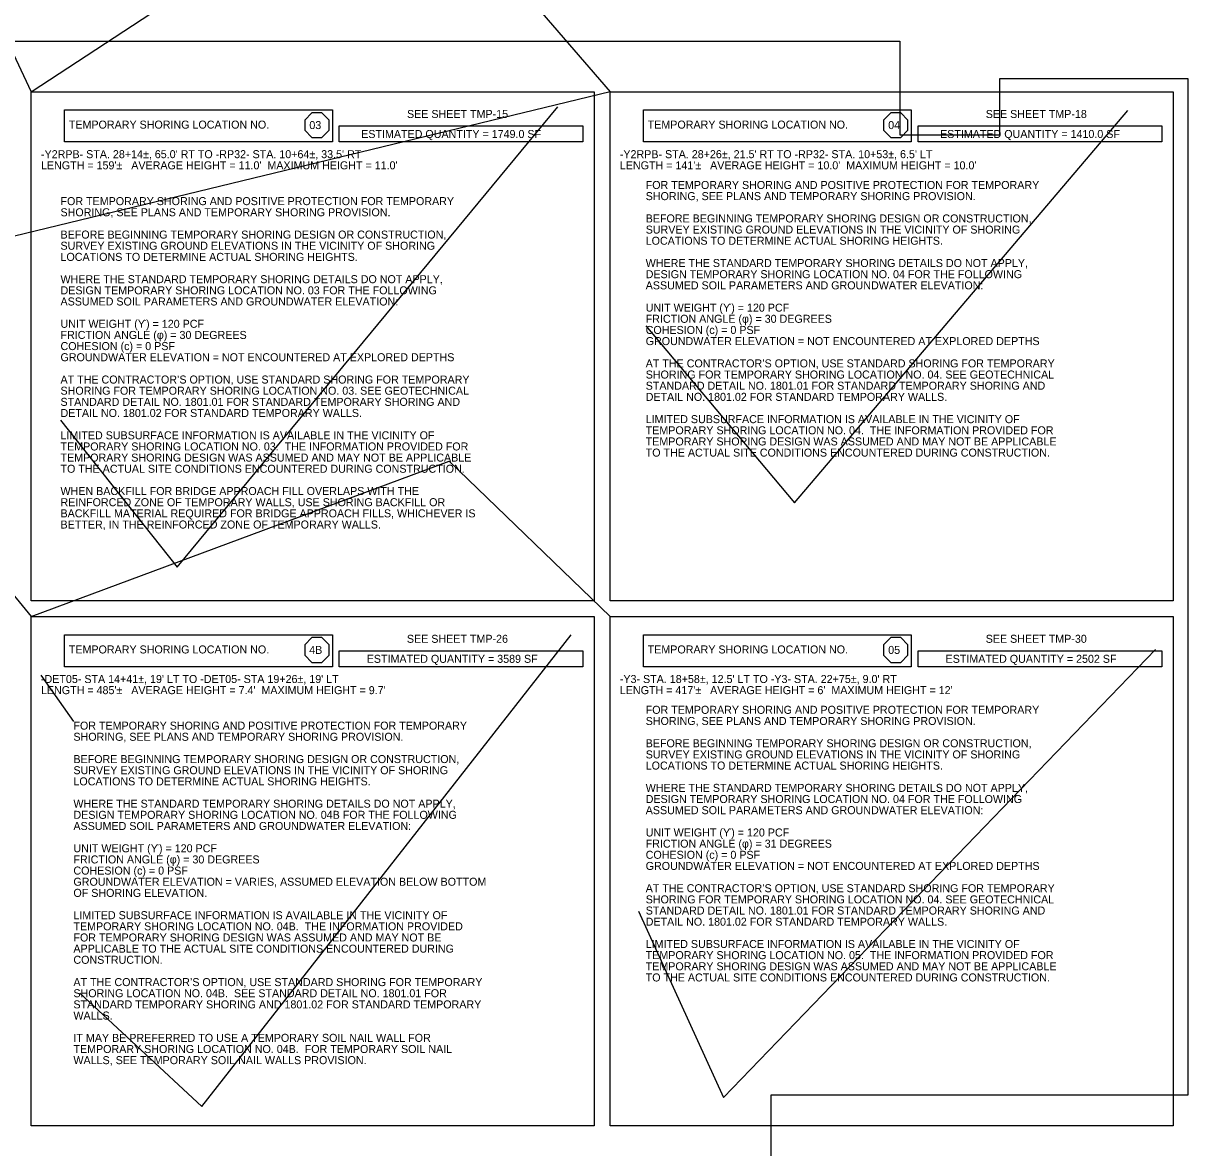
# Model space of a CAD drawing. Extents: x 2487012 to 2497594, y 369516 to 371986.
# Drawn here: x 2491299 to 2492290, y 370340 to 371297 of the extents above; entities that cross this region are included whole.
import ezdxf

# ---------------------------------------------------------------- set-up
doc = ezdxf.new("R2010")
doc.units = 0
for name, color, linetype in [('Scratch_Level_2', 7, 'Continuous'), ('Scratch_Level_4', 7, 'Continuous'), ('Scratch_Level_5', 7, 'Continuous'), ('Scratch_Level_6', 7, 'Continuous'), ('TC LABEL TEMP SHORING', 7, 'Continuous'), ('TC SHEET BORDER LINE THIN', 7, 'Continuous'), ('TC SHEET LAYOUT SHAPE', 7, 'Continuous'), ('TC SHEET TEXT', 7, 'Continuous')]:
    doc.layers.add(name, color=color, linetype=linetype)

msp = doc.modelspace()

# ---------------------------------------------------------------- linework, layer by layer
at = {"layer": 'Scratch_Level_2'}
for points in [[(2491330.49, 370959.46), (2491429.77, 370834.2), (2491753.99, 371226.17)], [(2491828.78, 371039.67), (2491955.41, 370889.07), (2492239.4, 371223.09)], [(2491347.09, 370471.61), (2491450.87, 370375.03), (2491765.44, 370776.66)]]:
    msp.add_lwpolyline(points, dxfattribs=at)
at = {"layer": 'Scratch_Level_4'}
msp.add_lwpolyline([(2491822.75, 370541.29), (2491895.16, 370382.73), (2492262.82, 370764.24)], dxfattribs=at)
at = {"layer": 'Scratch_Level_5'}
msp.add_line((2491313.86, 370742.45), (2491341.49, 370702.77), dxfattribs=at)
at = {"layer": 'Scratch_Level_6'}
msp.add_lwpolyline([(2490800.31, 371282.27), (2490812.63, 371239.13), (2491214.19, 371433.43), (2491305.53, 371239.13), (2491620.29, 371445.42), (2491798.43, 371239.13), (2490627, 370955.22), (2490812.63, 370792.26), (2491172.91, 370953.89), (2491305.53, 370792.26), (2491661.57, 370924.58), (2491798.43, 370792.26)], dxfattribs=at)
at = {"layer": 'TC LABEL TEMP SHORING'}
for p, q in [((2491544.49, 371221.17), (2491538.4, 371215.01)), ((2491538.4, 371215.01), (2491538.4, 371206.28)), ((2491553.1, 371221.17), (2491544.49, 371221.17)), ((2491559.18, 371215.01), (2491553.1, 371221.17)), ((2491559.18, 371206.28), (2491559.18, 371215.01)), ((2492037.38, 371221.17), (2492031.3, 371215.01)), ((2492031.3, 371215.01), (2492031.3, 371206.28)), ((2492045.99, 371221.17), (2492037.38, 371221.17)), ((2492052.08, 371215.01), (2492045.99, 371221.17)), ((2492052.08, 371206.28), (2492052.08, 371215.01)), ((2491538.4, 371206.28), (2491544.49, 371200.12)), ((2491553.1, 371200.12), (2491559.18, 371206.28)), ((2492031.3, 371206.28), (2492037.38, 371200.12)), ((2492045.99, 371200.12), (2492052.08, 371206.28)), ((2491544.49, 371200.12), (2491553.1, 371200.12)), ((2492037.38, 371200.12), (2492045.99, 371200.12)), ((2491544.49, 370774.3), (2491538.4, 370768.13)), ((2491538.4, 370768.13), (2491538.4, 370759.41)), ((2491553.1, 370774.3), (2491544.49, 370774.3)), ((2491559.18, 370768.13), (2491553.1, 370774.3)), ((2491559.18, 370759.41), (2491559.18, 370768.13)), ((2492037.38, 370774.3), (2492031.3, 370768.13)), ((2492031.3, 370768.13), (2492031.3, 370759.41)), ((2492045.99, 370774.3), (2492037.38, 370774.3)), ((2492052.08, 370768.13), (2492045.99, 370774.3)), ((2492052.08, 370759.41), (2492052.08, 370768.13)), ((2491538.4, 370759.41), (2491544.49, 370753.24)), ((2491553.1, 370753.24), (2491559.18, 370759.41)), ((2492031.3, 370759.41), (2492037.38, 370753.24)), ((2492045.99, 370753.24), (2492052.08, 370759.41)), ((2491544.49, 370753.24), (2491553.1, 370753.24)), ((2492037.38, 370753.24), (2492045.99, 370753.24))]:
    msp.add_line(p, q, dxfattribs=at)
at = {"layer": 'TC SHEET BORDER LINE THIN'}
for points in [[(2491305.53, 371239.13), (2491784.97, 371239.13), (2491784.97, 370805.5), (2491305.53, 370805.5)], [(2491798.43, 371239.13), (2492277.87, 371239.13), (2492277.87, 370805.5), (2491798.43, 370805.5)], [(2491334.02, 371223.55), (2491562.07, 371223.55), (2491562.07, 371196.29), (2491334.02, 371196.29)], [(2491826.91, 371223.55), (2492054.97, 371223.55), (2492054.97, 371196.29), (2491826.91, 371196.29)], [(2491567.83, 371209.92), (2491775.3, 371209.92), (2491775.3, 371196.29), (2491567.83, 371196.29)], [(2492060.73, 371209.92), (2492268.2, 371209.92), (2492268.2, 371196.29), (2492060.73, 371196.29)], [(2491305.53, 370792.26), (2491784.97, 370792.26), (2491784.97, 370358.63), (2491305.53, 370358.63)], [(2491798.43, 370792.26), (2492277.87, 370792.26), (2492277.87, 370358.63), (2491798.43, 370358.63)], [(2491334.02, 370776.68), (2491562.07, 370776.68), (2491562.07, 370749.42), (2491334.02, 370749.42)], [(2491826.91, 370776.68), (2492054.97, 370776.68), (2492054.97, 370749.42), (2491826.91, 370749.42)], [(2491567.83, 370763.05), (2491775.3, 370763.05), (2491775.3, 370749.42), (2491567.83, 370749.42)], [(2492060.73, 370763.05), (2492268.2, 370763.05), (2492268.2, 370749.42), (2492060.73, 370749.42)]]:
    msp.add_lwpolyline(points, close=True, dxfattribs=at)
at = {"layer": 'TC SHEET LAYOUT SHAPE'}
msp.add_lwpolyline([(2490800.31, 370690.84), (2490800.31, 371000.16), (2490800.31, 371272.27), (2490810.31, 371282.27), (2491253.33, 371282.27), (2491724.31, 371282.27), (2492045.31, 371282.27), (2492045.31, 371202.27), (2492130.31, 371202.27), (2492130.31, 371250.27), (2492290.31, 371250.27), (2492290.31, 370915.3), (2492290.31, 370636.1), (2492290.31, 370384.77), (2491935.31, 370384.77), (2491935.31, 370242.27), (2491562.13, 370242.27), (2491392.66, 370242.27), (2491039.89, 370242.27), (2490800.31, 370242.27)], close=True, dxfattribs=at)

# ---------------------------------------------------------------- texts
at = {"layer": 'TC LABEL TEMP SHORING'}
for s, p in [('03', (2491542.38, 371207.28)), ('04', (2492035.28, 371207.28)), ('4B', (2491542.27, 370760.41)), ('05', (2492035.28, 370760.41))]:
    msp.add_text(s, height=6.814, dxfattribs=at).set_placement(p)
at = {"layer": 'TC SHEET BORDER LINE THIN'}
for s, height, p in [('FOR TEMPORARY SHORING AND POSITIVE PROTECTION FOR TEMPORARY ', 6.8137, (2491828.78, 371156.28)), ('SHORING, SEE PLANS AND TEMPORARY SHORING PROVISION.', 6.8137, (2491828.78, 371146.79)), ('FOR TEMPORARY SHORING AND POSITIVE PROTECTION FOR TEMPORARY ', 6.8137, (2491330.49, 371142.53)), ('SHORING, SEE PLANS AND TEMPORARY SHORING PROVISION.', 6.8137, (2491330.49, 371133.04)), ('BEFORE BEGINNING TEMPORARY SHORING DESIGN OR CONSTRUCTION, ', 6.8137, (2491828.78, 371127.8)), ('SURVEY EXISTING GROUND ELEVATIONS IN THE VICINITY OF SHORING ', 6.8137, (2491828.78, 371118.3)), ('BEFORE BEGINNING TEMPORARY SHORING DESIGN OR CONSTRUCTION, ', 6.8137, (2491330.49, 371114.05)), ('LOCATIONS TO DETERMINE ACTUAL SHORING HEIGHTS.', 6.8137, (2491828.78, 371108.81)), ('SURVEY EXISTING GROUND ELEVATIONS IN THE VICINITY OF SHORING ', 6.8137, (2491330.49, 371104.55)), ('LOCATIONS TO DETERMINE ACTUAL SHORING HEIGHTS.', 6.8137, (2491330.49, 371095.06)), ('WHERE THE STANDARD TEMPORARY SHORING DETAILS DO NOT APPLY, ', 6.8137, (2491828.78, 371089.82)), ('DESIGN TEMPORARY SHORING LOCATION NO. 04 FOR THE FOLLOWING ', 6.8137, (2491828.78, 371080.33)), ('WHERE THE STANDARD TEMPORARY SHORING DETAILS DO NOT APPLY, ', 6.8137, (2491330.49, 371076.07)), ('DESIGN TEMPORARY SHORING LOCATION NO. 03 FOR THE FOLLOWING ', 6.8137, (2491330.49, 371066.57)), ('ASSUMED SOIL PARAMETERS AND GROUNDWATER ELEVATION:', 6.8137, (2491828.78, 371070.83)), ('ASSUMED SOIL PARAMETERS AND GROUNDWATER ELEVATION:', 6.8137, (2491330.49, 371057.08)), ('UNIT WEIGHT (ϒ) = 120 PCF ', 6.8137, (2491828.78, 371051.84)), ('UNIT WEIGHT (ϒ) = 120 PCF ', 6.8137, (2491330.49, 371038.09)), ('FRICTION ANGLE (φ) = 30 DEGREES ', 6.8137, (2491828.78, 371042.35)), ('FRICTION ANGLE (φ) = 30 DEGREES ', 6.8137, (2491330.49, 371028.6)), ('COHESION (c) = 0 PSF ', 6.8137, (2491828.78, 371032.85)), ('COHESION (c) = 0 PSF ', 6.8137, (2491330.49, 371019.1)), ('GROUNDWATER ELEVATION = NOT ENCOUNTERED AT EXPLORED DEPTHS', 6.8137, (2491828.78, 371023.36)), ('GROUNDWATER ELEVATION = NOT ENCOUNTERED AT EXPLORED DEPTHS', 6.8137, (2491330.49, 371009.61)), ('AT THE CONTRACTOR’S OPTION, USE STANDARD SHORING FOR TEMPORARY ', 6.8137, (2491828.78, 371004.37)), ('AT THE CONTRACTOR’S OPTION, USE STANDARD SHORING FOR TEMPORARY ', 6.8137, (2491330.49, 370990.62)), ('SHORING FOR TEMPORARY SHORING LOCATION NO. 04. SEE GEOTECHNICAL ', 6.8137, (2491828.78, 370994.88)), ('SHORING FOR TEMPORARY SHORING LOCATION NO. 03. SEE GEOTECHNICAL ', 6.8137, (2491330.49, 370981.13)), ('STANDARD DETAIL NO. 1801.01 FOR STANDARD TEMPORARY SHORING AND ', 6.8137, (2491828.78, 370985.38)), ('STANDARD DETAIL NO. 1801.01 FOR STANDARD TEMPORARY SHORING AND ', 6.8137, (2491330.49, 370971.63)), ('DETAIL NO. 1801.02 FOR STANDARD TEMPORARY WALLS.', 6.8137, (2491828.78, 370975.89)), ('DETAIL NO. 1801.02 FOR STANDARD TEMPORARY WALLS.', 6.8137, (2491330.49, 370962.14)), ('LIMITED SUBSURFACE INFORMATION IS AVAILABLE IN THE VICINITY OF ', 6.8137, (2491828.78, 370956.9)), ('LIMITED SUBSURFACE INFORMATION IS AVAILABLE IN THE VICINITY OF ', 6.8137, (2491330.49, 370943.15)), ('TEMPORARY SHORING LOCATION NO. 04.  THE INFORMATION PROVIDED FOR ', 6.8137, (2491828.78, 370947.4)), ('TEMPORARY SHORING DESIGN WAS ASSUMED AND MAY NOT BE APPLICABLE ', 6.8137, (2491828.78, 370937.91)), ('TEMPORARY SHORING LOCATION NO. 03.  THE INFORMATION PROVIDED FOR ', 6.8137, (2491330.49, 370933.65)), ('TO THE ACTUAL SITE CONDITIONS ENCOUNTERED DURING CONSTRUCTION.', 6.8137, (2491828.78, 370928.42)), ('TEMPORARY SHORING DESIGN WAS ASSUMED AND MAY NOT BE APPLICABLE ', 6.8137, (2491330.49, 370924.16)), ('TO THE ACTUAL SITE CONDITIONS ENCOUNTERED DURING CONSTRUCTION.', 6.8137, (2491330.49, 370914.66)), ('WHEN BACKFILL FOR BRIDGE APPROACH FILL OVERLAPS WITH THE ', 6.8137, (2491330.49, 370895.68)), ('REINFORCED ZONE OF TEMPORARY WALLS, USE SHORING BACKFILL OR ', 6.8137, (2491330.49, 370886.18)), ('BACKFILL MATERIAL REQUIRED FOR BRIDGE APPROACH FILLS, WHICHEVER IS ', 6.8137, (2491330.49, 370876.69)), ('BETTER, IN THE REINFORCED ZONE OF TEMPORARY WALLS.', 6.8137, (2491330.49, 370867.19)), ('SHORING, SEE PLANS AND TEMPORARY SHORING PROVISION.', 6.8137, (2491828.78, 370699.91)), ('FOR TEMPORARY SHORING AND POSITIVE PROTECTION FOR TEMPORARY ', 6.8137, (2491828.78, 370709.41)), ('FOR TEMPORARY SHORING AND POSITIVE PROTECTION FOR TEMPORARY', 6.8137, (2491341.49, 370695.95)), ('SHORING, SEE PLANS AND TEMPORARY SHORING PROVISION. ', 6.8137, (2491341.49, 370686.46)), ('BEFORE BEGINNING TEMPORARY SHORING DESIGN OR CONSTRUCTION, ', 6.8137, (2491828.78, 370680.92)), ('SURVEY EXISTING GROUND ELEVATIONS IN THE VICINITY OF SHORING ', 6.8137, (2491828.78, 370671.43)), ('BEFORE BEGINNING TEMPORARY SHORING DESIGN OR CONSTRUCTION,', 6.8137, (2491341.49, 370667.47)), ('LOCATIONS TO DETERMINE ACTUAL SHORING HEIGHTS.', 6.8137, (2491828.78, 370661.94)), ('SURVEY EXISTING GROUND ELEVATIONS IN THE VICINITY OF SHORING', 6.8137, (2491341.49, 370657.98)), ('LOCATIONS TO DETERMINE ACTUAL SHORING HEIGHTS. ', 6.8137, (2491341.49, 370648.48)), ('WHERE THE STANDARD TEMPORARY SHORING DETAILS DO NOT APPLY, ', 6.8137, (2491828.78, 370642.95)), ('DESIGN TEMPORARY SHORING LOCATION NO. 04 FOR THE FOLLOWING ', 6.8137, (2491828.78, 370633.45)), ('WHERE THE STANDARD TEMPORARY SHORING DETAILS DO NOT APPLY,', 6.8137, (2491341.49, 370629.49)), ('ASSUMED SOIL PARAMETERS AND GROUNDWATER ELEVATION:', 6.8137, (2491828.78, 370623.96)), ('ASSUMED SOIL PARAMETERS AND GROUNDWATER ELEVATION: ', 6.8137, (2491341.49, 370610.5)), ('DESIGN TEMPORARY SHORING LOCATION NO. 04B FOR THE FOLLOWING ', 6.8137, (2491341.49, 370620)), ('UNIT WEIGHT (ϒ) = 120 PCF ', 6.8137, (2491828.78, 370604.97)), ('UNIT WEIGHT (ϒ) = 120 PCF ', 6.8137, (2491341.49, 370591.52)), ('FRICTION ANGLE (φ) = 31 DEGREES ', 6.8137, (2491828.78, 370595.48)), ('FRICTION ANGLE (φ) = 30 DEGREES ', 6.8137, (2491341.49, 370582.02)), ('COHESION (c) = 0 PSF ', 6.8137, (2491828.78, 370585.98)), ('COHESION (c) = 0 PSF ', 6.8137, (2491341.49, 370572.53)), ('GROUNDWATER ELEVATION = NOT ENCOUNTERED AT EXPLORED DEPTHS', 6.8137, (2491828.78, 370576.49)), ('GROUNDWATER ELEVATION = VARIES, ASSUMED ELEVATION BELOW BOTTOM ', 6.8137, (2491341.49, 370563.03)), ('OF SHORING ELEVATION. ', 6.8137, (2491341.49, 370553.54)), ('AT THE CONTRACTOR’S OPTION, USE STANDARD SHORING FOR TEMPORARY ', 6.8137, (2491828.78, 370557.5)), ('SHORING FOR TEMPORARY SHORING LOCATION NO. 04. SEE GEOTECHNICAL ', 6.8137, (2491828.78, 370548)), ('LIMITED SUBSURFACE INFORMATION IS AVAILABLE IN THE VICINITY OF ', 6.8137, (2491341.49, 370534.55)), ('STANDARD DETAIL NO. 1801.01 FOR STANDARD TEMPORARY SHORING AND ', 6.8137, (2491828.78, 370538.51)), ('TEMPORARY SHORING LOCATION NO. 04B.  THE INFORMATION PROVIDED ', 6.8137, (2491341.49, 370525.06)), ('DETAIL NO. 1801.02 FOR STANDARD TEMPORARY WALLS.', 6.8137, (2491828.78, 370529.01)), ('FOR TEMPORARY SHORING DESIGN WAS ASSUMED AND MAY NOT BE ', 6.8137, (2491341.49, 370515.56)), ('APPLICABLE TO THE ACTUAL SITE CONDITIONS ENCOUNTERED DURING', 6.8137, (2491341.49, 370506.07)), ('LIMITED SUBSURFACE INFORMATION IS AVAILABLE IN THE VICINITY OF ', 6.8137, (2491828.78, 370510.03)), ('CONSTRUCTION. ', 6.8137, (2491341.49, 370496.57)), ('TEMPORARY SHORING LOCATION NO. 05.  THE INFORMATION PROVIDED FOR ', 6.8137, (2491828.78, 370500.53)), ('TEMPORARY SHORING DESIGN WAS ASSUMED AND MAY NOT BE APPLICABLE ', 6.8137, (2491828.78, 370491.04)), ('TO THE ACTUAL SITE CONDITIONS ENCOUNTERED DURING CONSTRUCTION.', 6.8137, (2491828.78, 370481.54)), ('AT THE CONTRACTOR’S OPTION, USE STANDARD SHORING FOR TEMPORARY ', 6.8137, (2491341.49, 370477.58)), ('SHORING LOCATION NO. 04B.  SEE STANDARD DETAIL NO. 1801.01 FOR ', 6.8137, (2491341.49, 370468.09)), ('STANDARD TEMPORARY SHORING AND 1801.02 FOR STANDARD TEMPORARY ', 6.8137, (2491341.49, 370458.59)), ('WALLS. ', 6.814, (2491341.49, 370449.1)), ('IT MAY BE PREFERRED TO USE A TEMPORARY SOIL NAIL WALL FOR ', 6.8137, (2491341.49, 370430.11)), ('TEMPORARY SHORING LOCATION NO. 04B.  FOR TEMPORARY SOIL NAIL ', 6.8137, (2491341.49, 370420.62)), ('WALLS, SEE TEMPORARY SOIL NAIL WALLS PROVISION.', 6.8137, (2491341.49, 370411.12))]:
    msp.add_text(s, height=height, dxfattribs=at).set_placement(p)
at = {"layer": 'TC SHEET TEXT'}
for s, p in [('SEE SHEET TMP-15', (2491625.54, 371216.75)), ('SEE SHEET TMP-18', (2492118.34, 371216.75)), ('TEMPORARY SHORING LOCATION NO.', (2491337.58, 371207.68)), ('TEMPORARY SHORING LOCATION NO.', (2491830.48, 371207.68)), ('ESTIMATED QUANTITY = 1749.0 SF', (2491586.53, 371199.7)), ('ESTIMATED QUANTITY = 1410.0 SF', (2492079.43, 371199.7)), ("-Y2RPB- STA. 28+14±, 65.0' RT TO -RP32- STA. 10+64±, 33.5' RT", (2491313.86, 371182.51)), ("-Y2RPB- STA. 28+26±, 21.5' RT TO -RP32- STA. 10+53±, 6.5' LT", (2491806.76, 371182.51)), ("LENGTH = 159'±   AVERAGE HEIGHT = 11.0'  MAXIMUM HEIGHT = 11.0'", (2491313.86, 371173.02)), ("LENGTH = 141'±   AVERAGE HEIGHT = 10.0'  MAXIMUM HEIGHT = 10.0'", (2491806.76, 371173.02)), ('SEE SHEET TMP-26', (2491625.44, 370769.88)), ('SEE SHEET TMP-30', (2492118.31, 370769.88)), ('TEMPORARY SHORING LOCATION NO.', (2491337.58, 370760.81)), ('TEMPORARY SHORING LOCATION NO.', (2491830.48, 370760.81)), ('ESTIMATED QUANTITY = 3589 SF', (2491591.23, 370752.83)), ('ESTIMATED QUANTITY = 2502 SF', (2492084.13, 370752.83)), ("-DET05- STA 14+41±, 19' LT TO -DET05- STA 19+26±, 19' LT", (2491313.86, 370735.64)), ("-Y3- STA. 18+58±, 12.5' LT TO -Y3- STA. 22+75±, 9.0' RT", (2491806.76, 370735.64)), ("LENGTH = 485'±   AVERAGE HEIGHT = 7.4'  MAXIMUM HEIGHT = 9.7'", (2491313.86, 370726.15)), ("LENGTH = 417'±   AVERAGE HEIGHT = 6'  MAXIMUM HEIGHT = 12'", (2491806.76, 370726.15))]:
    msp.add_text(s, height=6.8137, dxfattribs=at).set_placement(p)

doc.saveas('drawing.dxf')
